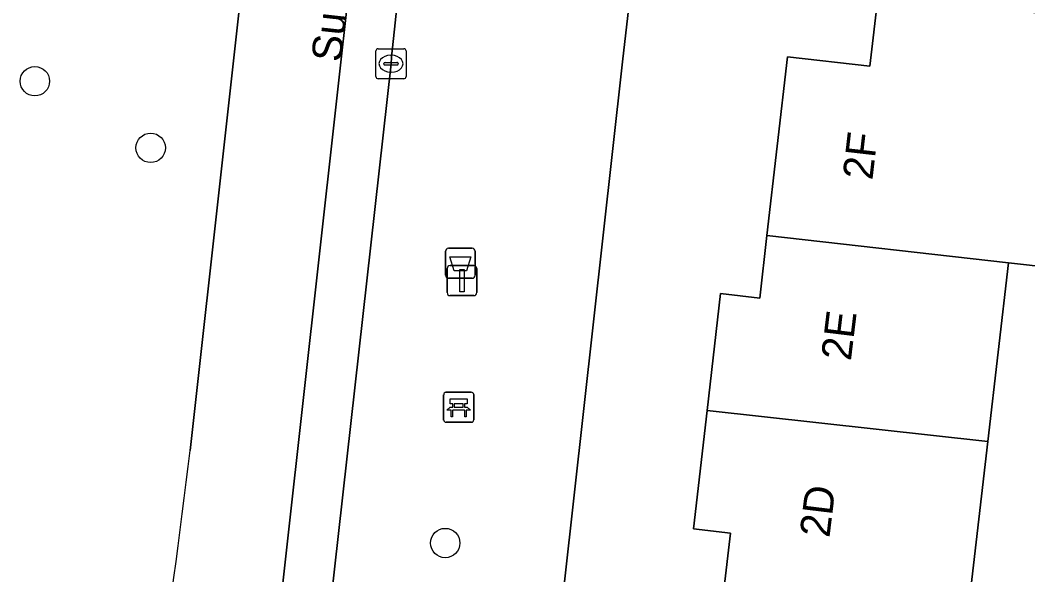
# Model space of a CAD drawing. Extents: x 162026 to 163502, y 387295 to 388169.
# Drawn here: x 162355.59 to 162389.15, y 387439.84 to 387458.34 of the extents above; entities that cross this region are included whole.
import ezdxf

# ---------------------------------------------------------------- set-up
doc = ezdxf.new("R2010")
doc.units = 0
for name, color, linetype in [('IMGEO_Afvalbak', 7, 'Continuous'), ('IMGEO_Bank', 7, 'Continuous'), ('IMGEO_Berm_groen', 7, 'Continuous'), ('IMGEO_Boom', 7, 'Continuous'), ('IMGEO_Erf', 7, 'Continuous'), ('IMGEO_Fietspad_gesloten', 7, 'Continuous'), ('IMGEO_Kolk', 7, 'Continuous'), ('IMGEO_Lichtmast', 7, 'Continuous'), ('IMGEO_Openbare_ruimte_label', 7, 'Continuous'), ('IMGEO_Pand', 7, 'Continuous'), ('IMGEO_Pand_nummerreeks', 7, 'Continuous'), ('IMGEO_Rijbaan_lokaal_gesloten', 7, 'Continuous'), ('IMGEO_Voetpad_open', 7, 'Continuous')]:
    doc.layers.add(name, color=color, linetype=linetype)

msp = doc.modelspace()

# ---------------------------------------------------------------- linework, layer by layer
at = {"layer": 'IMGEO_Afvalbak'}
for p, q in [((162369.855, 387450.729), (162370.645, 387450.729)), ((162370.645, 387450.729), (162369.855, 387450.729)), ((162369.755, 387449.829), (162369.755, 387450.629)), ((162369.755, 387450.629), (162369.755, 387449.829)), ((162370.745, 387450.629), (162370.745, 387449.829)), ((162370.745, 387449.829), (162370.745, 387450.629)), ((162370.645, 387449.729), (162369.855, 387449.729)), ((162369.855, 387449.729), (162370.645, 387449.729))]:
    msp.add_line(p, q, dxfattribs=at)
msp.add_lwpolyline([(162369.898, 387450.443), (162370.602, 387450.443), (162370.453, 387449.973), (162370.047, 387449.973), (162369.898, 387450.443)], dxfattribs=at)
for centre, start, end in [((162369.855, 387450.629), 90, 180), ((162369.855, 387450.629), 90, 180), ((162370.645, 387450.629), 0, 90), ((162370.645, 387450.629), 360, 90), ((162369.855, 387449.829), 180, 270), ((162369.855, 387449.829), 180, 270), ((162370.645, 387449.829), 270, 0), ((162370.645, 387449.829), 270, 0)]:
    msp.add_arc(centre, 0.1, start, end, dxfattribs=at)
at = {"layer": 'IMGEO_Bank'}
for p, q in [((162369.695, 387445.005), (162369.695, 387445.846)), ((162369.695, 387445.846), (162369.695, 387445.005)), ((162369.77, 387445.93), (162370.611, 387445.93)), ((162370.611, 387445.93), (162369.77, 387445.93)), ((162370.695, 387445.855), (162370.695, 387445.014)), ((162370.695, 387445.014), (162370.695, 387445.855)), ((162370.004, 387445.436), (162370.004, 387445.542)), ((162370.048, 387445.542), (162370.048, 387445.436)), ((162370.336, 387445.548), (162370.054, 387445.548)), ((162370.054, 387445.43), (162370.336, 387445.43)), ((162370.342, 387445.436), (162370.342, 387445.542)), ((162370.386, 387445.542), (162370.386, 387445.436)), ((162370.392, 387445.328), (162369.999, 387445.328)), ((162370.62, 387444.93), (162369.779, 387444.93)), ((162369.779, 387444.93), (162370.62, 387444.93))]:
    msp.add_line(p, q, dxfattribs=at)
for points in [[(162369.998, 387445.548), (162369.912, 387445.548), (162369.912, 387445.709), (162370.475, 387445.709), (162370.475, 387445.548), (162370.392, 387445.548)], [(162369.942, 387445.328), (162369.8, 387445.328), (162369.912, 387445.43), (162369.998, 387445.43)], [(162370.392, 387445.43), (162370.475, 387445.43), (162370.587, 387445.328), (162370.448, 387445.328)], [(162369.992, 387445.321), (162369.992, 387445.114), (162369.949, 387445.114), (162369.949, 387445.321)], [(162370.442, 387445.321), (162370.442, 387445.114), (162370.398, 387445.114), (162370.398, 387445.321)]]:
    msp.add_lwpolyline(points, dxfattribs=at)
for centre, radius, start, end in [((162369.773, 387445.852), 0.0779, 92.4484, 184.2845), ((162369.773, 387445.852), 0.0779, 92.4484, 184.2845), ((162370.617, 387445.852), 0.0779, 2.4484, 94.2845), ((162370.617, 387445.852), 0.0779, 2.4484, 94.2845), ((162369.997, 387445.541), 0.00671, 2.8957, 87.1043), ((162369.997, 387445.437), 0.00671, 272.8957, 357.1043), ((162370.054, 387445.541), 0.00671, 92.8957, 177.1043), ((162370.054, 387445.437), 0.00671, 182.8957, 267.1043), ((162370.336, 387445.541), 0.00671, 2.8957, 87.1043), ((162370.336, 387445.437), 0.00671, 272.8957, 357.1043), ((162370.393, 387445.541), 0.00671, 92.8957, 177.1043), ((162370.393, 387445.437), 0.00671, 182.8957, 267.1043), ((162369.773, 387445.008), 0.0779, 182.4484, 274.2845), ((162369.773, 387445.008), 0.0779, 182.4484, 274.2845), ((162369.942, 387445.321), 0.00671, 2.8957, 87.1043), ((162369.999, 387445.321), 0.00671, 92.8957, 177.1043), ((162370.391, 387445.321), 0.00671, 2.8957, 87.1043), ((162370.448, 387445.321), 0.00671, 92.8957, 177.1043), ((162370.617, 387445.008), 0.0779, 272.4484, 4.2845), ((162370.617, 387445.008), 0.0779, 272.4484, 4.2845)]:
    msp.add_arc(centre, radius, start, end, dxfattribs=at)
at = {"layer": 'IMGEO_Berm_groen'}
msp.add_lwpolyline([(162361.255, 387443.988), (162363.465, 387463.887), (162367.963, 387504.443)], dxfattribs=at)
msp.add_arc((161972.176, 387492.017), 392.032, 350.46924, 352.96278, dxfattribs=at)
at = {"layer": 'IMGEO_Boom'}
for centre in [(162356.078, 387456.301), (162359.936, 387454.079), (162369.747, 387440.904)]:
    msp.add_circle(centre, 0.489, dxfattribs=at)
at = {"layer": 'IMGEO_Erf'}
for points in [[(162377.752, 387439.384), (162379.017, 387439.241), (162379.247, 387441.236), (162378.017, 387441.378), (162378.471, 387445.326), (162378.919, 387449.221), (162380.223, 387449.071), (162380.463, 387451.159), (162381.147, 387457.113), (162383.889, 387456.798), (162384.164, 387459.183), (162377.94, 387459.884), (162376.15, 387460.086), (162376.131, 387460.234), (162376.03, 387460.239), (162375.655, 387456.942), (162371.134, 387416.396)], [(162391.38, 387449.925), (162388.505, 387450.25), (162387.82, 387444.289), (162387.137, 387438.348), (162387.134, 387438.321), (162385.833, 387438.468), (162385.806, 387438.236), (162385.147, 387432.501), (162384.462, 387426.543), (162383.777, 387420.583), (162383.641, 387419.398), (162383.201, 387415.569), (162385.799, 387415.271), (162386.677, 387414.163), (162386.331, 387411.152), (162391.662, 387409.78)]]:
    msp.add_lwpolyline(points, dxfattribs=at)
at = {"layer": 'IMGEO_Fietspad_gesloten'}
for points in [[(162367.941, 387456.884), (162367.962, 387457.104), (162368.361, 387460.854), (162368.714, 387463.921), (162373.113, 387503.254), (162371.444, 387503.441), (162363.403, 387431.184)], [(162364.983, 387430.263), (162365.039, 387430.868), (162365.797, 387437.657), (162367.941, 387456.884)]]:
    msp.add_lwpolyline(points, dxfattribs=at)
at = {"layer": 'IMGEO_Kolk'}
for p, q in [((162367.44, 387456.458), (162367.44, 387457.31)), ((162367.515, 387457.384), (162368.367, 387457.384)), ((162367.928, 387457.164), (162367.953, 387457.164)), ((162368.441, 387457.31), (162368.441, 387456.458)), ((162367.699, 387456.878), (162367.699, 387456.89)), ((162368.137, 387456.841), (162367.739, 387456.841)), ((162367.742, 387456.927), (162368.14, 387456.927)), ((162368.183, 387456.89), (162368.183, 387456.878)), ((162367.951, 387456.604), (162367.926, 387456.604)), ((162368.367, 387456.384), (162367.515, 387456.384))]:
    msp.add_line(p, q, dxfattribs=at)
for points in [[(162367.44, 387456.458), (162367.44, 387457.31)], [(162367.515, 387457.384), (162368.367, 387457.384)], [(162368.441, 387457.31), (162368.441, 387456.458)], [(162368.367, 387456.384), (162367.515, 387456.384)]]:
    msp.add_lwpolyline(points, dxfattribs=at)
for centre, radius, start, end in [((162367.517, 387457.308), 0.0765, 91.552, 178.448), ((162367.517, 387457.308), 0.0765, 91.552, 178.448), ((162368.365, 387457.308), 0.0765, 1.552, 88.448), ((162368.365, 387457.308), 0.0765, 1.552, 88.448), ((162367.739, 387456.887), 0.0403, 85.8775, 175.7526), ((162367.736, 387456.877), 0.0366, 178.938, 274.7102), ((162368.14, 387456.884), 0.043, 264.8664, 352.4533), ((162368.144, 387456.889), 0.0386, 1.7309, 96.639), ((162367.517, 387456.46), 0.0765, 181.552, 268.448), ((162367.517, 387456.46), 0.0765, 181.552, 268.448), ((162368.365, 387456.46), 0.0765, 271.552, 358.448), ((162368.365, 387456.46), 0.0765, 271.552, 358.448)]:
    msp.add_arc(centre, radius, start, end, dxfattribs=at)
for centre, major_axis, ratio, start_param, end_param in [((162367.927, 387456.884), (-0.387, 0.002), 0.722429, 4.712389, 7.853982), ((162367.952, 387456.884), (-0.39, 0.002), 0.717154, 1.570796, 4.712389)]:
    msp.add_ellipse(centre, major_axis=major_axis, ratio=ratio, start_param=start_param, end_param=end_param, dxfattribs=at)
at = {"layer": 'IMGEO_Lichtmast'}
for p, q in [((162369.81, 387449.251), (162369.81, 387450.051)), ((162369.81, 387450.051), (162369.81, 387449.251)), ((162369.91, 387450.151), (162370.7, 387450.151)), ((162370.7, 387450.151), (162369.91, 387450.151)), ((162370.8, 387450.051), (162370.8, 387449.251)), ((162370.8, 387449.251), (162370.8, 387450.051)), ((162370.7, 387449.151), (162369.91, 387449.151)), ((162369.91, 387449.151), (162370.7, 387449.151))]:
    msp.add_line(p, q, dxfattribs=at)
msp.add_lwpolyline([(162370.23, 387450.026), (162370.38, 387450.026), (162370.38, 387449.276), (162370.23, 387449.276), (162370.23, 387450.026)], dxfattribs=at)
for centre, start, end in [((162369.91, 387450.051), 90, 180), ((162369.91, 387450.051), 90, 180), ((162370.7, 387450.051), 0, 90), ((162370.7, 387450.051), 360, 90), ((162369.91, 387449.251), 180, 270), ((162369.91, 387449.251), 180, 270), ((162370.7, 387449.251), 270, 0), ((162370.7, 387449.251), 270, 0)]:
    msp.add_arc(centre, 0.1, start, end, dxfattribs=at)
at = {"layer": 'IMGEO_Pand'}
for points in [[(162392.061, 387455.86), (162392.771, 387455.778), (162393.046, 387458.163), (162384.164, 387459.183), (162383.889, 387456.798), (162381.147, 387457.113), (162380.463, 387451.159), (162388.505, 387450.25), (162391.38, 387449.925)], [(162380.463, 387451.159), (162380.223, 387449.071), (162378.919, 387449.221), (162378.471, 387445.326), (162387.82, 387444.289), (162388.505, 387450.25)], [(162387.82, 387444.289), (162378.471, 387445.326), (162378.017, 387441.378), (162379.247, 387441.236), (162379.017, 387439.241), (162385.833, 387438.468), (162387.134, 387438.321), (162387.137, 387438.348)]]:
    msp.add_lwpolyline(points, close=True, dxfattribs=at)
at = {"layer": 'IMGEO_Rijbaan_lokaal_gesloten'}
for points in [[(162371.444, 387503.441), (162373.113, 387503.254), (162373.146, 387503.547), (162373.181, 387503.861), (162367.963, 387504.443), (162363.465, 387463.887), (162361.255, 387443.988)], [(162363.403, 387431.184), (162371.444, 387503.441)]]:
    msp.add_lwpolyline(points, dxfattribs=at)
msp.add_arc((161972.176, 387492.017), 392.032, 350.46924, 352.96278, dxfattribs=at)
at = {"layer": 'IMGEO_Voetpad_open'}
for points in [[(162368.714, 387463.921), (162368.361, 387460.854), (162367.962, 387457.104), (162367.941, 387456.884), (162365.797, 387437.657)], [(162367.108, 387422.786), (162367.19, 387421.816), (162366.853, 387417.815), (162371.134, 387416.396), (162375.655, 387456.942), (162376.03, 387460.239), (162376.131, 387460.234), (162376.477, 387463.277)]]:
    msp.add_lwpolyline(points, dxfattribs=at)

# ---------------------------------------------------------------- texts
at = {"layer": 'IMGEO_Openbare_ruimte_label'}
msp.add_text('Suikerpeerstraat', height=1, rotation=83.7421, dxfattribs=at).set_placement((162366.28, 387456.916))
at = {"layer": 'IMGEO_Pand_nummerreeks'}
for s, rotation, p in [('2F', 83.4456, (162383.975, 387452.984)), ('2E', 83.0901, (162383.257, 387446.957)), ('2D', 83.0732, (162382.543, 387441.061))]:
    msp.add_text(s, height=1, rotation=rotation, dxfattribs=at).set_placement(p)

doc.saveas('drawing.dxf')
